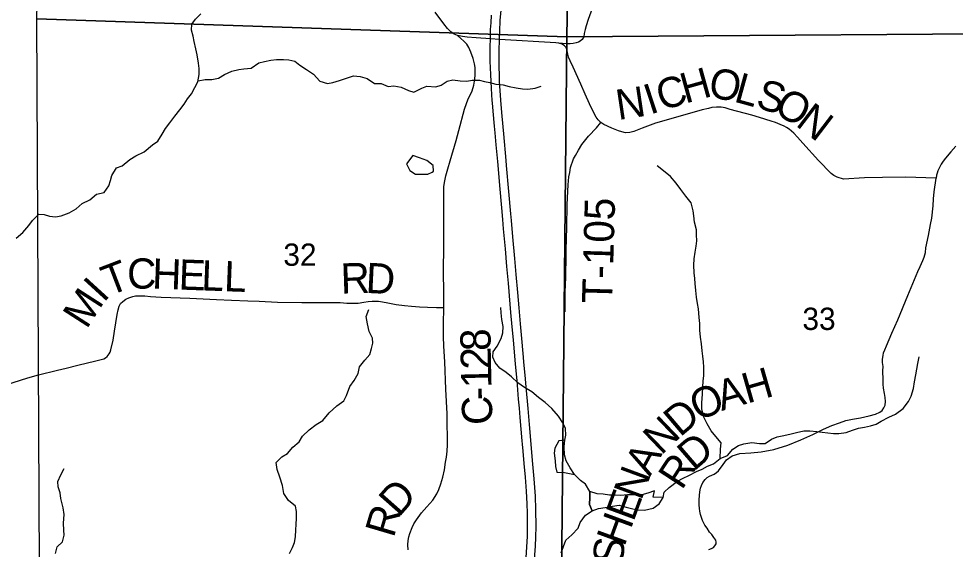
# Model space of a CAD drawing. Extents: x 0 to 34, y 0 to 22.
# Drawn here: x 6.329 to 8.087, y 15.58 to 16.577 of the extents above; entities that cross this region are included whole.
import ezdxf

# ---------------------------------------------------------------- set-up
doc = ezdxf.new("R2010")
doc.units = 0
for name, color, linetype in [('GM_X_Corporation', 7, 'Continuous'), ('GM_X_County_Road', 7, 'Continuous'), ('GM_X_County_Road_Text', 7, 'Continuous'), ('GM_X_Interstate_Route', 7, 'Continuous'), ('GM_X_Minor_Lake', 7, 'Continuous'), ('GM_X_Minor_River', 7, 'Continuous'), ('GM_X_Section_Text', 7, 'Continuous'), ('GM_X_Township_Road', 7, 'Continuous'), ('GM_X_Township_Road_Text', 7, 'Continuous')]:
    doc.layers.add(name, color=color, linetype=linetype)

msp = doc.modelspace()

# ---------------------------------------------------------------- linework, layer by layer
at = {"layer": 'GM_X_Corporation'}
for points in [[(6.3854, 17.5878), (7.375, 17.5696), (7.3577, 16.5425), (6.3626, 16.5761)], [(7.375, 17.5696), (8.4063, 17.5538), (8.3875, 16.5502), (7.3577, 16.5425)], [(7.3577, 16.5425), (7.3478, 15.5216), (6.4093, 15.5478), (6.3676, 15.5481), (6.3626, 16.5761)], [(8.3875, 16.5502), (8.3939, 15.4987), (7.4137, 15.5211), (7.3478, 15.5216), (7.3577, 16.5425)]]:
    msp.add_lwpolyline(points, close=True, dxfattribs=at)
at = {"layer": 'GM_X_County_Road'}
for points in [[(7.3609, 16.5051), (7.3597, 16.5102), (7.3582, 16.5163), (7.357, 16.5206), (7.3557, 16.5232), (7.3533, 16.5259), (7.349, 16.529), (7.3427, 16.5309), (7.3371, 16.5315), (7.2313, 16.5377), (7.2145, 16.539), (7.1877, 16.5405), (7.1704, 16.5418), (7.1617, 16.5429), (7.1523, 16.5451), (7.1461, 16.5478), (7.1398, 16.5522), (7.1334, 16.5582), (7.1269, 16.5667), (7.1104, 16.5886)], [(7.0597, 15.5792), (7.0593, 15.5885), (7.0597, 15.5971), (7.0609, 15.6035), (7.063, 15.6103), (7.0671, 15.621), (7.0706, 15.6282), (7.0753, 15.6358), (7.0847, 15.6488), (7.0949, 15.6603), (7.1062, 15.6728), (7.1137, 15.6845), (7.1172, 15.6929), (7.1213, 15.7032), (7.1252, 15.7156), (7.1281, 15.7293), (7.13, 15.7439), (7.1319, 15.7534), (7.1333, 15.7648), (7.1336, 15.7762), (7.1337, 15.7845), (7.1335, 15.7959), (7.1333, 15.8111), (7.1328, 15.8345), (7.1306, 15.8812), (7.1287, 15.9324), (7.127, 15.9615), (7.1262, 15.9797), (7.1261, 16.0033), (7.1268, 16.0344), (7.1268, 16.0619), (7.1259, 16.1025), (7.1261, 16.1161), (7.1266, 16.136), (7.1267, 16.1673), (7.1268, 16.1956), (7.1267, 16.2281), (7.1267, 16.2425), (7.1268, 16.2505), (7.1269, 16.2614), (7.1284, 16.2722), (7.1303, 16.2817), (7.1341, 16.2947), (7.1385, 16.3096), (7.1499, 16.3478), (7.1552, 16.3669), (7.1657, 16.4066), (7.1722, 16.4259), (7.1791, 16.4395), (7.1818, 16.4472), (7.183, 16.4518), (7.1842, 16.4591), (7.1855, 16.47), (7.1857, 16.4772), (7.1857, 16.485), (7.1844, 16.492), (7.1817, 16.5019), (7.1776, 16.5136), (7.1739, 16.5224), (7.17, 16.5287), (7.1645, 16.5346), (7.1587, 16.5396), (7.1523, 16.5451)], [(8.0884, 16.3371), (8.0789, 16.3268), (8.0687, 16.3146), (8.0644, 16.309), (8.0608, 16.3036), (8.0573, 16.2971), (8.0546, 16.2908), (8.0529, 16.2866), (8.0519, 16.2829), (8.0513, 16.2773), (7.9939, 16.2788), (7.9505, 16.2786), (7.9167, 16.2778), (7.8774, 16.2754), (7.8655, 16.2789), (7.859, 16.2819), (7.8539, 16.2859), (7.8305, 16.3105), (7.801, 16.3432), (7.7909, 16.354), (7.7839, 16.3616), (7.7794, 16.3657), (7.7751, 16.3689), (7.7704, 16.3721), (7.7655, 16.3747), (7.7583, 16.3781), (7.7494, 16.3815), (7.7414, 16.3842), (7.7197, 16.391), (7.7051, 16.3953), (7.6642, 16.4064), (7.6552, 16.4091), (7.6476, 16.4105), (7.6389, 16.4108), (7.6303, 16.4096), (7.6237, 16.4082), (7.6117, 16.4052), (7.566, 16.3924), (7.5242, 16.3802), (7.4992, 16.371), (7.4835, 16.3647), (7.4759, 16.3627), (7.4682, 16.3625), (7.4608, 16.3642), (7.455, 16.366), (7.442, 16.3713), (7.4273, 16.378), (7.4218, 16.3817), (7.4168, 16.3865), (7.413, 16.3915), (7.4079, 16.4009), (7.4002, 16.4169), (7.3924, 16.435), (7.384, 16.4537), (7.3697, 16.4858), (7.3642, 16.4978), (7.3611, 16.5041), (7.3609, 16.5051)]]:
    msp.add_lwpolyline(points, dxfattribs=at)
at = {"layer": 'GM_X_Interstate_Route'}
for points in [[(7.2812, 15.5641), (7.2837, 15.6048), (7.284, 15.6305), (7.2838, 15.6484), (7.2834, 15.6659), (7.2821, 15.6893), (7.2802, 15.7156), (7.2778, 15.7416), (7.2759, 15.7647), (7.2748, 15.7779), (7.2742, 15.7839), (7.2702, 15.8281), (7.2689, 15.8453), (7.2673, 15.8622), (7.2642, 15.897), (7.2616, 15.9277), (7.2575, 15.9735), (7.2554, 15.9981), (7.2529, 16.0252), (7.2516, 16.0403), (7.2481, 16.0802), (7.2454, 16.1115), (7.2426, 16.1442), (7.239, 16.1818), (7.2374, 16.1994), (7.2356, 16.2214), (7.2319, 16.2637), (7.2307, 16.2792), (7.228, 16.3083), (7.2252, 16.3396), (7.2233, 16.3622), (7.222, 16.375), (7.2196, 16.4032), (7.2182, 16.4184), (7.2178, 16.4231), (7.2162, 16.4455), (7.2148, 16.472), (7.214, 16.4968), (7.214, 16.5168), (7.2141, 16.5241), (7.2145, 16.539), (7.2147, 16.5566), (7.2154, 16.5688), (7.2161, 16.5835)], [(7.2965, 15.5534), (7.2987, 15.5861), (7.2993, 15.603), (7.2999, 15.623), (7.2998, 15.6553), (7.2989, 15.6803), (7.2964, 15.7128), (7.2932, 15.7469), (7.2899, 15.7855), (7.2874, 15.8147), (7.2849, 15.845), (7.2811, 15.8856), (7.2793, 15.9072), (7.2771, 15.9319), (7.2762, 15.9413), (7.2726, 15.983), (7.2707, 16.0037), (7.2684, 16.0337), (7.2657, 16.0623), (7.2627, 16.0965), (7.26, 16.1265), (7.2564, 16.1671), (7.2537, 16.1977), (7.2525, 16.2104), (7.2488, 16.252), (7.2446, 16.301), (7.2437, 16.3103), (7.2394, 16.3604), (7.2364, 16.3937), (7.2347, 16.4153), (7.2316, 16.4588), (7.2315, 16.4676), (7.2307, 16.4892), (7.2307, 16.5163), (7.2313, 16.5377), (7.2318, 16.553), (7.2328, 16.573), (7.2348, 16.5992)]]:
    msp.add_lwpolyline(points, dxfattribs=at)
at = {"layer": 'GM_X_Minor_Lake'}
for points in [[(7.0686, 16.32), (7.0566, 16.304), (7.0627, 16.2915), (7.0737, 16.2844), (7.0968, 16.2845), (7.1049, 16.2887)], [(7.1049, 16.2887), (7.1077, 16.2902), (7.1066, 16.3008), (7.0948, 16.3106), (7.0811, 16.3155), (7.0686, 16.32)], [(7.3538, 15.785), (7.3425, 15.7838), (7.3353, 15.7701), (7.3342, 15.7606), (7.3358, 15.7466), (7.3365, 15.7356), (7.3392, 15.7254), (7.3532, 15.7247), (7.3722, 15.721)], [(7.3722, 15.721), (7.3638, 15.7331), (7.3562, 15.7463), (7.3535, 15.7577), (7.3527, 15.7728), (7.3538, 15.785)], [(7.4007, 15.6888), (7.4011, 15.6778), (7.4004, 15.6642), (7.4053, 15.6528), (7.417, 15.6567), (7.4299, 15.659), (7.4432, 15.6613), (7.456, 15.6629), (7.4693, 15.6595), (7.4814, 15.6561), (7.4909, 15.6547), (7.5034, 15.6539), (7.52, 15.6578), (7.5314, 15.6654), (7.5389, 15.6776)], [(7.5389, 15.6776), (7.52, 15.6783), (7.5222, 15.6904), (7.5101, 15.6858), (7.4984, 15.6827), (7.4851, 15.6823), (7.4715, 15.6823), (7.459, 15.6815), (7.4488, 15.6822), (7.4378, 15.6821), (7.4257, 15.6836), (7.4147, 15.6843), (7.4007, 15.6888)]]:
    msp.add_lwpolyline(points, dxfattribs=at)
at = {"layer": 'GM_X_Minor_River'}
for points in [[(6.324, 16.1646), (6.3364, 16.1752), (6.3474, 16.1882), (6.3545, 16.198), (6.3666, 16.2095), (6.3765, 16.2091), (6.3863, 16.2061), (6.3977, 16.2043), (6.4086, 16.2062), (6.4234, 16.2123), (6.4363, 16.2199), (6.4476, 16.2298), (6.4619, 16.2363), (6.4748, 16.247), (6.4892, 16.2501), (6.4978, 16.2626), (6.5008, 16.2729), (6.5035, 16.2824), (6.5121, 16.2968), (6.5227, 16.3006), (6.5374, 16.3124), (6.5488, 16.3193), (6.5639, 16.3269), (6.5798, 16.3399), (6.5896, 16.3467), (6.5979, 16.36), (6.6043, 16.3703), (6.6122, 16.3809), (6.6216, 16.3935), (6.6314, 16.4056), (6.639, 16.4159), (6.6454, 16.4261), (6.6533, 16.4357), (6.659, 16.4474), (6.665, 16.4581), (6.6672, 16.4717), (6.6672, 16.4831), (6.6664, 16.4929), (6.6637, 16.5089), (6.661, 16.5198), (6.6583, 16.5335), (6.6564, 16.5437), (6.653, 16.5551), (6.6537, 16.5661), (6.6605, 16.5756), (6.6707, 16.5855)], [(6.6653, 16.4598), (6.6786, 16.4623), (6.6911, 16.4623), (6.704, 16.465), (6.7153, 16.4719), (6.7289, 16.478), (6.7418, 16.4811), (6.7516, 16.4823), (6.7649, 16.4838), (6.7792, 16.4937), (6.7898, 16.4964), (6.8023, 16.4987), (6.8129, 16.5003), (6.8258, 16.5), (6.8356, 16.4992), (6.847, 16.4966), (6.8565, 16.4891), (6.869, 16.4812), (6.8819, 16.4725), (6.8937, 16.4593), (6.9085, 16.4551), (6.9187, 16.4571), (6.9308, 16.4605), (6.944, 16.4647), (6.9569, 16.4693), (6.9698, 16.4679), (6.983, 16.4645), (6.9967, 16.4547), (7.0092, 16.4551), (7.0224, 16.4491), (7.0327, 16.4503), (7.047, 16.448), (7.0607, 16.4416), (7.0702, 16.4386), (7.0853, 16.4459), (7.0951, 16.4497), (7.1118, 16.4486), (7.122, 16.4521), (7.1333, 16.4593), (7.1436, 16.4616), (7.1572, 16.4598), (7.1697, 16.4595), (7.1803, 16.461), (7.1935, 16.4611), (7.203, 16.4584), (7.2129, 16.457), (7.2246, 16.454), (7.2382, 16.4525), (7.2492, 16.4491), (7.2629, 16.4469), (7.2746, 16.4451), (7.2848, 16.4443), (7.2981, 16.4459), (7.3098, 16.4501)], [(7.6458, 15.7511), (7.6465, 15.7682), (7.6473, 15.7803), (7.6378, 15.7924), (7.629, 15.803), (7.6214, 15.8162), (7.6149, 15.8283), (7.6115, 15.8439), (7.6115, 15.8556), (7.6122, 15.8719), (7.6129, 15.8852), (7.614, 15.8962), (7.6147, 15.9068), (7.615, 15.9224), (7.6143, 15.9322), (7.6131, 15.9432), (7.6119, 15.9527), (7.6104, 15.9659), (7.6088, 15.9784), (7.6076, 15.9917), (7.6072, 16.0046), (7.6061, 16.0156), (7.6049, 16.0319), (7.6033, 16.0417), (7.6014, 16.0535), (7.6002, 16.0663), (7.599, 16.0796), (7.5979, 16.0891), (7.5967, 16.0997), (7.5959, 16.1137), (7.5966, 16.1259), (7.5985, 16.1384), (7.6007, 16.1497), (7.6018, 16.1596), (7.6014, 16.1706), (7.601, 16.1801), (7.5972, 16.1945), (7.596, 16.2066), (7.5952, 16.2161), (7.591, 16.2308), (7.5811, 16.2433), (7.572, 16.2562), (7.5629, 16.2675), (7.5523, 16.2804), (7.5394, 16.2909), (7.5276, 16.3004)], [(6.8372, 15.5727), (6.8425, 15.5837), (6.8463, 15.5932), (6.8485, 15.6039), (6.8492, 15.6168), (6.8496, 15.627), (6.8499, 15.6387), (6.8499, 15.6516), (6.8483, 15.6615), (6.8351, 15.6721), (6.8267, 15.6849), (6.824, 15.7001), (6.819, 15.7156), (6.8141, 15.7304), (6.8117, 15.7432), (6.8227, 15.7539), (6.8333, 15.76), (6.8431, 15.7722), (6.8552, 15.7821), (6.8616, 15.7927), (6.8737, 15.8045), (6.8869, 15.8144), (6.8997, 15.8224), (6.9118, 15.8365), (6.9258, 15.8498), (6.939, 15.8589), (6.9443, 15.8692), (6.9503, 15.8859), (6.9582, 15.8973), (6.9657, 15.9102), (6.9683, 15.9227), (6.9785, 15.9353), (6.9876, 15.9459), (6.9913, 15.9573), (6.9936, 15.9676), (6.9928, 15.977), (6.9867, 15.9895), (6.9832, 16.0039), (6.9809, 16.0176), (6.9858, 16.0305)], [(7.4053, 15.6528), (7.4004, 15.6642), (7.4011, 15.6778), (7.4007, 15.6888), (7.3931, 15.7025), (7.3836, 15.7096), (7.3722, 15.721), (7.3638, 15.7331), (7.3562, 15.7463), (7.3535, 15.7577), (7.3527, 15.7728), (7.3538, 15.785), (7.3557, 15.7948), (7.3553, 15.8073), (7.3503, 15.8176), (7.3423, 15.8304), (7.3298, 15.8444), (7.3173, 15.8557), (7.3044, 15.8652), (7.2922, 15.8757), (7.2785, 15.8844), (7.266, 15.8931), (7.2539, 15.9044), (7.244, 15.912), (7.2319, 15.9203), (7.2231, 15.9308), (7.2189, 15.9411), (7.2193, 15.9509), (7.2272, 15.9619), (7.2344, 15.9764), (7.2374, 15.987), (7.2385, 15.9984), (7.2358, 16.0116), (7.2342, 16.0245), (7.2338, 16.0344)], [(7.9164, 15.8097), (7.9281, 15.812), (7.9383, 15.8154), (7.9482, 15.8208), (7.9621, 15.8284), (7.975, 15.8338), (7.989, 15.8448), (7.9995, 15.8577), (8.0044, 15.868), (8.0086, 15.8824), (8.0104, 15.8949), (8.013, 15.9082), (8.0149, 15.9184), (8.0167, 15.9294), (8.019, 15.9419)], [(7.3473, 15.5734), (7.3518, 15.5856), (7.3559, 15.5973), (7.3672, 15.6076), (7.3789, 15.6201), (7.3827, 15.6308), (7.3929, 15.6445), (7.4053, 15.6528), (7.417, 15.6567), (7.4299, 15.659), (7.4432, 15.6613), (7.456, 15.6629), (7.4693, 15.6595), (7.4814, 15.6561), (7.4909, 15.6547), (7.5034, 15.6539), (7.52, 15.6578), (7.5314, 15.6654), (7.5389, 15.6776), (7.5404, 15.6878), (7.5502, 15.6962), (7.5657, 15.708), (7.5763, 15.7137), (7.5869, 15.7187), (7.6012, 15.7263), (7.6118, 15.7309), (7.6216, 15.7362), (7.633, 15.7408), (7.6458, 15.7511), (7.6595, 15.7565), (7.6693, 15.7686), (7.6802, 15.7755), (7.6901, 15.7786), (7.7048, 15.7809), (7.7192, 15.7787), (7.7302, 15.7791), (7.7423, 15.7871), (7.7525, 15.7917), (7.7654, 15.794), (7.779, 15.7971), (7.7892, 15.7994), (7.8028, 15.8025), (7.8142, 15.8029), (7.8271, 15.8014), (7.8369, 15.8003), (7.8475, 15.7992), (7.8585, 15.7977), (7.8687, 15.7978), (7.8823, 15.7997), (7.8941, 15.8039), (7.9054, 15.8077), (7.9164, 15.8097)], [(6.3977, 15.5723), (6.4007, 15.5848), (6.4109, 15.5943), (6.4138, 15.6069), (6.4131, 15.6163), (6.413, 15.6296), (6.4141, 15.6455), (6.4118, 15.658), (6.408, 15.6755), (6.4064, 15.6861), (6.403, 15.6978), (6.4018, 15.7077), (6.4078, 15.7202), (6.4138, 15.7323)]]:
    msp.add_lwpolyline(points, dxfattribs=at)
at = {"layer": 'GM_X_Township_Road'}
for points in [[(7.4051, 16.5955), (7.3981, 16.5751), (7.3941, 16.5633), (7.3922, 16.5563), (7.3905, 16.5487), (7.3895, 16.5428), (7.3868, 16.5378), (7.383, 16.5342), (7.3799, 16.5326), (7.3753, 16.5313), (7.3698, 16.5302), (7.3639, 16.5296), (7.3565, 16.5297), (7.3498, 16.5303), (7.3427, 16.5309)], [(7.3567, 16.1422), (7.3576, 16.185), (7.3585, 16.2275), (7.3605, 16.2649), (7.3617, 16.2794), (7.3631, 16.2881), (7.3649, 16.2972), (7.3705, 16.3133), (7.374, 16.32), (7.3798, 16.33), (7.3862, 16.3405), (7.3985, 16.356), (7.4132, 16.3719), (7.4218, 16.3817)], [(7.6245, 15.5801), (7.6292, 15.5819), (7.6334, 15.5839), (7.6358, 15.5867), (7.6379, 15.5907), (7.6379, 15.594), (7.6372, 15.5974), (7.634, 15.6023), (7.6299, 15.6079), (7.6257, 15.6126), (7.6214, 15.6199), (7.617, 15.6259), (7.6126, 15.6345), (7.6087, 15.6454), (7.6073, 15.6522), (7.6068, 15.6571), (7.6062, 15.6637), (7.606, 15.6687), (7.606, 15.6741), (7.6076, 15.6884), (7.6085, 15.6951), (7.6106, 15.7003), (7.6132, 15.7055), (7.6177, 15.7115), (7.6214, 15.715), (7.6257, 15.7178), (7.6345, 15.7216), (7.6388, 15.7248), (7.6426, 15.7276), (7.6513, 15.7396), (7.6575, 15.7486), (7.6679, 15.7558), (7.6823, 15.7604), (7.7035, 15.7612), (7.7228, 15.7636), (7.7464, 15.768), (7.7729, 15.7758), (7.7974, 15.7857), (7.8196, 15.7959), (7.8398, 15.8062), (7.8552, 15.8129), (7.8696, 15.818), (7.8818, 15.8219), (7.894, 15.8246), (7.9091, 15.8274), (7.9257, 15.831), (7.937, 15.8339), (7.9452, 15.8379), (7.9495, 15.8412), (7.9531, 15.8458), (7.9554, 15.8507), (7.9562, 15.8579), (7.9552, 15.8655), (7.9539, 15.8731), (7.9521, 15.883), (7.9514, 15.8907), (7.9516, 15.8987), (7.951, 15.9157), (7.9514, 15.9237), (7.9507, 15.9311), (7.9507, 15.9372), (7.9514, 15.9441), (7.9526, 15.9492), (7.9548, 15.9551), (7.9579, 15.9623), (7.9678, 15.9864), (7.979, 16.0114), (7.9979, 16.0569), (8.0166, 16.1019), (8.0211, 16.1114), (8.0261, 16.1224), (8.0286, 16.129), (8.0309, 16.1374), (8.0321, 16.1463), (8.037, 16.1696), (8.0403, 16.1905), (8.0429, 16.2024), (8.0457, 16.2254), (8.0463, 16.2386), (8.0475, 16.2516), (8.0513, 16.2773)], [(7.3546, 16.0265), (7.3544, 16.0359), (7.3546, 16.045), (7.3549, 16.0631), (7.3557, 16.0904), (7.3565, 16.1333), (7.3567, 16.1422)], [(6.3046, 15.889), (6.346, 15.9024), (6.3656, 15.908), (6.4015, 15.9167), (6.4178, 15.9206), (6.4399, 15.9262), (6.4734, 15.9342), (6.4886, 15.9382), (6.4916, 15.9399), (6.4944, 15.9423), (6.4965, 15.9447), (6.4984, 15.9474), (6.5001, 15.9505), (6.5018, 15.9548), (6.5061, 15.9732), (6.5086, 15.9899), (6.5134, 16.021), (6.5154, 16.03), (6.5175, 16.0368), (6.52, 16.0416), (6.5241, 16.0459), (6.5296, 16.0498), (6.5352, 16.0525), (6.5431, 16.0552), (6.5481, 16.0562), (6.5541, 16.0565), (6.5653, 16.056), (6.5762, 16.0551), (6.5958, 16.0535), (6.6502, 16.0519), (6.7002, 16.0491), (6.7283, 16.0479), (6.7589, 16.0467), (6.7802, 16.046), (6.8142, 16.0444), (6.8603, 16.0435), (6.8904, 16.0438), (6.9088, 16.0436), (6.9321, 16.0438), (6.9449, 16.0427), (6.9537, 16.0422), (6.966, 16.0427), (6.9767, 16.0442), (6.9845, 16.0456), (6.9924, 16.0461), (6.9983, 16.0462), (7.0042, 16.046), (7.0116, 16.0452), (7.0216, 16.0434), (7.0375, 16.0401), (7.053, 16.0381), (7.0663, 16.0369), (7.081, 16.0356), (7.0962, 16.0347), (7.113, 16.0343), (7.1268, 16.0344)]]:
    msp.add_lwpolyline(points, dxfattribs=at)

# ---------------------------------------------------------------- texts
at = {"layer": 'GM_X_County_Road_Text'}
for s, rotation, p in [('H', 15.5481, (7.5801, 16.417)), ('O', 349.8639, (7.6216, 16.43)), ('C', 17.0933, (7.5359, 16.4033)), ('L', 344.5167, (7.6695, 16.4215)), ('S', 343.7864, (7.7103, 16.4103)), ('N', 8.4598, (7.4542, 16.3863)), ('I', 18.3232, (7.5141, 16.3961)), ('O', 329.9971, (7.7438, 16.401)), ('N', 322.572, (7.7854, 16.377)), ('8', 90.9866, (7.215, 15.9532)), ('2', 91.2111, (7.2157, 15.9185)), ('1', 91.3298, (7.2165, 15.8839)), ('-', 91.4141, (7.2171, 15.8608)), ('C', 91.4422, (7.2182, 15.8145)), ('D', 48.5156, (7.0426, 15.6396)), ('R', 73.5748, (7.0326, 15.6005))]:
    msp.add_text(s, height=0.0568, rotation=rotation, dxfattribs=at).set_placement(p)
at = {"layer": 'GM_X_Section_Text'}
for s, p in [('32', (6.8255, 16.1126)), ('33', (7.8001, 15.9922))]:
    msp.add_text(s, height=0.04186, rotation=0, dxfattribs=at).set_placement(p)
at = {"layer": 'GM_X_Township_Road_Text'}
for s, height, rotation, p in [('T-105', 0.05682, 88.3577, (7.4428, 16.0414)), ('C', 0.0568, 0.3122, (6.5323, 16.0696)), ('H', 0.0568, 357.956, (6.5784, 16.0699)), ('E', 0.0568, 357.9168, (6.6283, 16.0681)), ('T', 0.0568, 20.9403, (6.4979, 16.0554)), ('L', 0.0568, 357.9167, (6.6708, 16.0666)), ('L', 0.0568, 357.9124, (6.7133, 16.065)), ('R', 0.0568, 1.8465, (6.9339, 16.0603)), ('D', 0.0568, 357.256, (6.9793, 16.0618)), ('I', 0.0568, 47.573, (6.4879, 16.0421)), ('M', 0.0568, 57.2479, (6.4561, 15.9922)), ('H', 0.0568, 15.9459, (7.6963, 15.8537)), ('A', 0.0568, 16.0209, (7.6483, 15.8399)), ('O', 0.0568, 24.5217, (7.6049, 15.8199)), ('D', 0.0568, 40.3508, (7.5703, 15.7898)), ('N', 0.0568, 43.7558, (7.5348, 15.7558)), ('D', 0.0568, 40.87, (7.5964, 15.726)), ('A', 0.0568, 61.6704, (7.5139, 15.7155)), ('R', 0.0568, 56.7819, (7.5736, 15.69)), ('N', 0.0568, 69.762, (7.4975, 15.6705)), ('E', 0.0568, 69.7745, (7.4828, 15.6306)), ('H', 0.0568, 69.8933, (7.4656, 15.5837)), ('S', 0.0568, 83.017, (7.4618, 15.549))]:
    msp.add_text(s, height=height, rotation=rotation, dxfattribs=at).set_placement(p)

doc.saveas('drawing.dxf')
